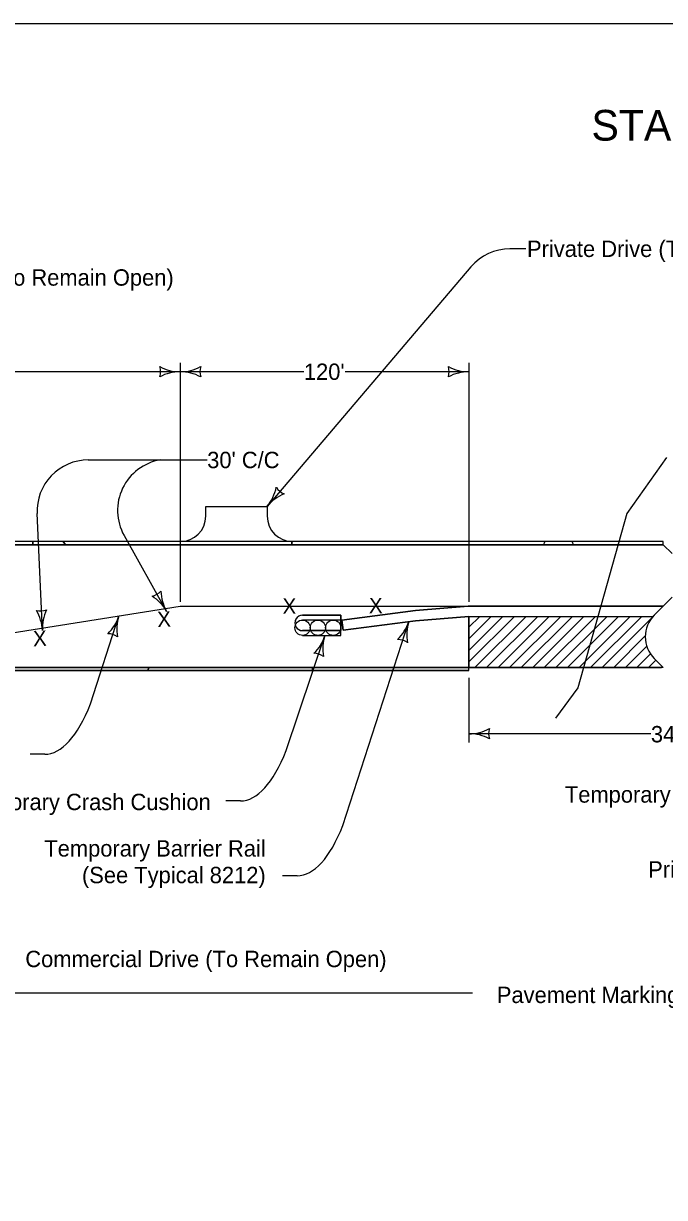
# Model space of a CAD drawing. Extents: x -2134934 to -2127057, y -2139046 to -2137036.
# Drawn here: x -2129305 to -2128679, y -2138183 to -2137036 of the extents above; entities that cross this region are included whole.
import ezdxf

# ---------------------------------------------------------------- set-up
doc = ezdxf.new("R2010")
doc.units = 0
for name, color, linetype in [('Barrier', 7, 'Continuous'), ('BridgeSuperStructureExisting', 7, 'Continuous'), ('Default', 7, 'Continuous'), ('DsnShtInsideBorder', 7, 'Continuous'), ('DsnShtPlotIdentification', 7, 'Continuous'), ('DsnShtPlotShape', 7, 'Continuous')]:
    doc.layers.add(name, color=color, linetype=linetype)

msp = doc.modelspace()

# ---------------------------------------------------------------- linework, layer by layer
at = {"layer": 'BridgeSuperStructureExisting'}
for p, q in [((-2128814.5, -2137256.1), (-2128830, -2137256.1)), ((-2128868.1, -2137273.7), (-2129067.3, -2137507.7)), ((-2129152.3, -2137367.6), (-2129152.3, -2137601.1)), ((-2128870.1, -2137367.6), (-2128870.1, -2137601.1)), ((-2129152.3, -2137376.2), (-2129320.9, -2137376.2)), ((-2129031.4, -2137376.2), (-2129152.3, -2137376.2)), ((-2128870.1, -2137376.2), (-2128990.9, -2137376.2)), ((-2129242.2, -2137462.4), (-2129125.9, -2137462.4)), ((-2129287, -2137629.1), (-2129292.2, -2137514.7)), ((-2129207.1, -2137536.1), (-2129165.6, -2137610.4)), ((-2128680.1, -2137545.2), (-2130182.6, -2137545.2)), ((-2129042.3, -2137542.2), (-2129152.3, -2137542.2)), ((-2128680.1, -2137545.2), (-2128671.3, -2137553.9)), ((-2128671.3, -2137553.9), (-2128680.1, -2137545.2)), ((-2128671.3, -2137596.4), (-2128688.9, -2137613.9)), ((-2129530.1, -2137665.2), (-2129152.3, -2137605.2)), ((-2129152.3, -2137605.2), (-2128870.7, -2137605.2)), ((-2128870.7, -2137605.2), (-2128922.2, -2137609.5)), ((-2128922.2, -2137609.5), (-2128870.7, -2137605.2)), ((-2128922.2, -2137609.5), (-2128870.7, -2137605.2)), ((-2128680.1, -2137605.2), (-2128870.7, -2137605.2)), ((-2128870.7, -2137605.2), (-2128680.1, -2137605.2)), ((-2128870.7, -2137605.2), (-2128680.1, -2137605.2)), ((-2128688.9, -2137613.9), (-2128680.1, -2137605.2)), ((-2129240, -2137700.8), (-2129212.2, -2137614.7)), ((-2129032.7, -2137614.1), (-2128995.2, -2137614.1)), ((-2128995.2, -2137618.8), (-2129032.7, -2137618.8)), ((-2128995.2, -2137614.1), (-2128995.2, -2137629.1)), ((-2128995.2, -2137633.8), (-2128995.2, -2137618.8)), ((-2128922.2, -2137609.5), (-2128994.2, -2137618.8)), ((-2128994.2, -2137618.8), (-2128922.2, -2137609.5)), ((-2128994.2, -2137618.8), (-2128922.2, -2137609.5)), ((-2128994.2, -2137618.8), (-2128992.9, -2137628.7)), ((-2128992.9, -2137628.7), (-2128994.2, -2137618.8)), ((-2128992.9, -2137628.7), (-2128994.2, -2137618.8)), ((-2128993.3, -2137819.5), (-2128928.9, -2137620.3)), ((-2128992.9, -2137628.7), (-2128922.4, -2137619.5)), ((-2128922.4, -2137619.5), (-2128992.9, -2137628.7)), ((-2128922.4, -2137619.5), (-2128992.9, -2137628.7)), ((-2128922.4, -2137619.5), (-2128870.3, -2137615.2)), ((-2128870.3, -2137615.2), (-2128922.4, -2137619.5)), ((-2128870.1, -2137615.2), (-2128922.4, -2137619.5)), ((-2128870.3, -2137615.2), (-2128690.1, -2137615.2)), ((-2128870.3, -2137615.2), (-2128690.1, -2137615.2)), ((-2128825.6, -2137615.2), (-2128870.1, -2137659.7)), ((-2128870.1, -2137615.2), (-2128870.1, -2137665.2)), ((-2128836.9, -2137615.2), (-2128870.1, -2137648.4)), ((-2128848.2, -2137615.2), (-2128870.1, -2137637.1)), ((-2128859.5, -2137615.2), (-2128870.1, -2137625.8)), ((-2128870.1, -2137665.2), (-2128870.1, -2137615.2)), ((-2128814.3, -2137615.2), (-2128864.3, -2137665.2)), ((-2128802.9, -2137615.2), (-2128852.9, -2137665.2)), ((-2128791.6, -2137615.2), (-2128841.6, -2137665.2)), ((-2128780.3, -2137615.2), (-2128830.3, -2137665.2)), ((-2128769, -2137615.2), (-2128819, -2137665.2)), ((-2128757.7, -2137615.2), (-2128807.7, -2137665.2)), ((-2128746.4, -2137615.2), (-2128796.4, -2137665.2)), ((-2128735.1, -2137615.2), (-2128785.1, -2137665.2)), ((-2128723.8, -2137615.2), (-2128773.8, -2137665.2)), ((-2128712.4, -2137615.2), (-2128762.4, -2137665.2)), ((-2128701.1, -2137615.2), (-2128751.1, -2137665.2)), ((-2128691.3, -2137616.6), (-2128739.8, -2137665.2)), ((-2128995.2, -2137629.1), (-2129032.7, -2137629.1)), ((-2129048.7, -2137746.4), (-2129010.8, -2137633.8)), ((-2129032.7, -2137633.8), (-2128995.2, -2137633.8)), ((-2128697.7, -2137634.3), (-2128728.5, -2137665.2)), ((-2128696.3, -2137644.3), (-2128717.2, -2137665.2)), ((-2128692.6, -2137651.9), (-2128705.9, -2137665.2)), ((-2130182.6, -2137665.2), (-2128870.1, -2137665.2)), ((-2128687.3, -2137657.9), (-2128694.6, -2137665.2)), ((-2128688.9, -2137656.4), (-2128680.1, -2137665.2)), ((-2128870.1, -2137675.2), (-2128870.1, -2137738.5)), ((-2128692.2, -2137729.8), (-2128870.1, -2137729.8)), ((-2129284.7, -2137749.9), (-2129298.9, -2137749.9)), ((-2129093.4, -2137795.5), (-2129107.7, -2137795.5)), ((-2129038, -2137868.7), (-2129052.2, -2137868.7)), ((-2128866.5, -2137983.3), (-2129530.1, -2137983.3))]:
    msp.add_line(p, q, dxfattribs=at)
for points in [[(-2128677, -2137459.9), (-2128715.6, -2137514.8), (-2128763.5, -2137684.9), (-2128785.5, -2137714.7)], [(-2129127.3, -2137517.2), (-2129127.3, -2137507.7), (-2129067.3, -2137507.7), (-2129067.3, -2137517.2)], [(-2128680.1, -2137605.2), (-2128680.1, -2137605.2), (-2128671.3, -2137596.4)], [(-2128690.1, -2137615.2), (-2128690.1, -2137615.2)], [(-2128680.1, -2137665.2), (-2128870.1, -2137665.2)]]:
    msp.add_lwpolyline(points, dxfattribs=at)
for centre in [(-2129032.7, -2137626.3), (-2129032.7, -2137626.3), (-2129017.7, -2137626.3), (-2129017.7, -2137626.3), (-2129002.7, -2137626.3), (-2129002.7, -2137626.3)]:
    msp.add_circle(centre, 7.5, dxfattribs=at)
for centre, radius, start, end in [((-2128830, -2137306.1), 50, 90, 139.587), ((-2129242.2, -2137512.4), 50, 90, 182.6154), ((-2129163.4, -2137511.7), 50.1, 99.6171, 209.1999), ((-2129152.3, -2137517.2), 25, 270, 360), ((-2129042.3, -2137517.2), 25, 180, 270), ((-2129032.7, -2137621.6), 7.5, 89.9996, 270), ((-2128667.7, -2137635.2), 30, 135, 225), ((-2128667.7, -2137635.2), 30, 135, 138.2713), ((-2128870.1, -2137687.4), 42.5, 270, 298.0725), ((-2128870.1, -2137772.3), 42.5, 61.9275, 90), ((-2128834.5, -2137729.8), 16.4, 162.2666, 197.7334)]:
    msp.add_arc(centre, radius, start, end, dxfattribs=at)
for centre in [(-2129284.7, -2137537), (-2129093.4, -2137582.6), (-2129038, -2137655.7)]:
    msp.add_ellipse(centre, major_axis=(0, -212.9), ratio=0.328743, start_param=0, end_param=0.693162, dxfattribs=at)
at = {"layer": 'Default'}
msp.add_lwpolyline([(-2130232, -2137035.9), (-2127097, -2137035.9), (-2127097, -2139045.9), (-2130232, -2139045.9)], close=True, dxfattribs=at)
at = {"layer": 'DsnShtInsideBorder'}
for p, q in [((-2128995.2, -2137614.1), (-2129032.7, -2137614.1)), ((-2128995.2, -2137629.1), (-2128995.2, -2137614.1)), ((-2129032.7, -2137629.1), (-2128995.2, -2137629.1))]:
    msp.add_line(p, q, dxfattribs=at)
msp.add_arc((-2129032.7, -2137621.6), 7.5, 90.0024, 269.9972, dxfattribs=at)
at = {"layer": 'DsnShtPlotIdentification'}
for p, q in [((-2128680.1, -2137542.2), (-2130182.6, -2137542.2)), ((-2128680.1, -2137545.2), (-2130182.6, -2137545.2)), ((-2129296.4, -2137542.2), (-2129329.6, -2137542.2)), ((-2129329.6, -2137545.2), (-2129296.2, -2137545.2)), ((-2129266.6, -2137542.2), (-2129296.4, -2137542.2)), ((-2129296.4, -2137542.2), (-2129296.2, -2137545.2)), ((-2129296.2, -2137545.2), (-2129296.4, -2137542.2)), ((-2129296.2, -2137545.2), (-2129264.4, -2137545.2)), ((-2129266.6, -2137542.2), (-2129264.4, -2137545.2)), ((-2129043.1, -2137542.2), (-2129266.6, -2137542.2)), ((-2129264.4, -2137545.2), (-2129266.6, -2137542.2)), ((-2129264.4, -2137545.2), (-2129043.1, -2137545.2)), ((-2128796.1, -2137542.2), (-2129043.1, -2137542.2)), ((-2129043.1, -2137542.2), (-2129043.1, -2137545.2)), ((-2129043.1, -2137545.2), (-2129043.1, -2137542.2)), ((-2129043.1, -2137545.2), (-2128797, -2137545.2)), ((-2128797, -2137545.2), (-2128768.2, -2137545.2)), ((-2128769.2, -2137542.2), (-2128796.1, -2137542.2)), ((-2128680.1, -2137542.2), (-2128769.2, -2137542.2)), ((-2128768.2, -2137545.2), (-2128680.1, -2137545.2)), ((-2128680.1, -2137545.2), (-2128680.1, -2137542.2)), ((-2130182, -2137665.2), (-2128682, -2137665.2)), ((-2129182.9, -2137665.2), (-2129475.9, -2137665.2)), ((-2129183.9, -2137668.2), (-2129182.9, -2137665.2)), ((-2129182.9, -2137665.2), (-2129183.9, -2137668.2)), ((-2129022.5, -2137665.2), (-2129182.9, -2137665.2)), ((-2129023.4, -2137668.2), (-2129022.5, -2137665.2)), ((-2129022.5, -2137665.2), (-2129023.4, -2137668.2)), ((-2128943.4, -2137665.2), (-2129022.5, -2137665.2)), ((-2128944.3, -2137668.2), (-2128943.4, -2137665.2)), ((-2128943.4, -2137665.2), (-2128944.3, -2137668.2)), ((-2128870.8, -2137665.2), (-2128943.4, -2137665.2)), ((-2128870.1, -2137665.2), (-2128870.8, -2137665.2)), ((-2128870.1, -2137668.2), (-2128870.1, -2137665.2)), ((-2128870.1, -2137668.2), (-2128870.1, -2137665.2)), ((-2129497.6, -2137668.2), (-2129183.9, -2137668.2)), ((-2129183.9, -2137668.2), (-2129023.4, -2137668.2)), ((-2129023.4, -2137668.2), (-2128944.3, -2137668.2)), ((-2128944.3, -2137668.2), (-2128870.1, -2137668.2))]:
    msp.add_line(p, q, dxfattribs=at)
for points in [[(-2130182.4, -2137545.2), (-2128872.4, -2137545.2)], [(-2128870.1, -2137665.2), (-2130182.6, -2137665.2)], [(-2128870.1, -2137668.2), (-2130182.6, -2137668.2)]]:
    msp.add_lwpolyline(points, dxfattribs=at)
for start, end in [(156.382, 168.6701), (156.382, 168.6701), (11.3299, 23.618), (11.3299, 23.618)]:
    msp.add_arc((-2128782.6, -2137548), 14.7, start, end, dxfattribs=at)
at = {"layer": 'DsnShtPlotShape'}
for centre, radius, start, end in [((-2129187.9, -2137376.2), 16.4, 342.2666, 17.7334), ((-2129152.3, -2137333.7), 42.5, 241.9275, 270), ((-2129152.3, -2137418.7), 42.5, 90, 118.0725), ((-2129152.3, -2137333.7), 42.5, 270, 298.0725), ((-2129152.3, -2137418.7), 42.5, 61.9275, 90), ((-2129116.6, -2137376.2), 16.4, 162.2666, 197.7334), ((-2128905.8, -2137376.2), 16.4, 342.2666, 17.7334), ((-2128870.1, -2137333.7), 42.5, 241.9275, 270), ((-2128870.1, -2137418.7), 42.5, 90, 118.0725), ((-2129100, -2137480.5), 42.5, 320.2932, 348.3657), ((-2129044.5, -2137480.3), 16.4, 212.5598, 248.0266), ((-2129034.6, -2137534.8), 42.5, 112.2207, 140.2932), ((-2129183.2, -2137579.4), 16.4, 281.9035, 317.3702), ((-2129202.5, -2137631.4), 42.5, 29.6368, 57.7093), ((-2129128.6, -2137589.4), 42.5, 181.5643, 209.6368), ((-2129288.6, -2137593.5), 16.4, 254.8821, 290.3488), ((-2129329.4, -2137631), 42.5, 2.6154, 30.6879), ((-2129244.5, -2137627.1), 42.5, 154.5429, 182.6154), ((-2129252.6, -2137601.6), 42.5, 314.0124, 342.0849), ((-2129171.7, -2137627.8), 42.5, 162.0849, 190.1574), ((-2128969.3, -2137607.3), 42.5, 314.0124, 342.0849), ((-2128888.4, -2137633.4), 42.5, 162.0849, 190.1574), ((-2129223.1, -2137648.6), 16.4, 54.3516, 89.8183), ((-2129051.2, -2137620.8), 42.5, 314.0124, 342.0849), ((-2128970.4, -2137646.9), 42.5, 162.0849, 190.1574), ((-2128939.8, -2137654.2), 16.4, 54.3516, 89.8183), ((-2129021.8, -2137667.7), 16.4, 54.3516, 89.8183)]:
    msp.add_arc(centre, radius, start, end, dxfattribs=at)

# ---------------------------------------------------------------- texts
at = {"layer": 'Barrier'}
msp.add_text('STAGE 2', height=30, dxfattribs=at).set_placement((-2128750.3, -2137150.4))
at = {"layer": 'BridgeSuperStructureExisting'}
for s, height, p in [('Private Drive (To Remain Open)', 16, (-2128813.3, -2137264.1)), ('Private Drive (To Remain Open)', 16, (-2129464.2, -2137292.1)), ("120'", 16, (-2129031.4, -2137384.2)), ("30' C/C", 16, (-2129125.9, -2137470.4)), ('X', 15, (-2129052.3, -2137612.7)), ('X', 15, (-2128967.8, -2137612.1)), ("343'", 16, (-2128692.2, -2137738.3)), ('Temporary Crash Cushion', 16, (-2128776.3, -2137797.2)), ('Temporary Crash Cushion', 16, (-2129373.3, -2137804.5)), ('Temporary Barrier Rail', 16, (-2129285.1, -2137849.9)), ('(See Typical 8212)', 16, (-2129248.3, -2137875.9)), ('Private Drive (To Remain Open)', 16, (-2128694.9, -2137870.4)), ('Commercial Drive (To Remain Open)', 16, (-2129303.7, -2137957.9)), ('Pavement Marking Removal Limits', 16, (-2128842.8, -2137993))]:
    msp.add_text(s, height=height, dxfattribs=at).set_placement(p)
for p in [(-2129174.5, -2137625.7), (-2129295.9, -2137644.4)]:
    msp.add_text('X', height=15, rotation=2.011, dxfattribs=at).set_placement(p)

doc.saveas('drawing.dxf')
